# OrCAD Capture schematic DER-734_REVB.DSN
size B; title: DER-734 RevB; rev: RevB
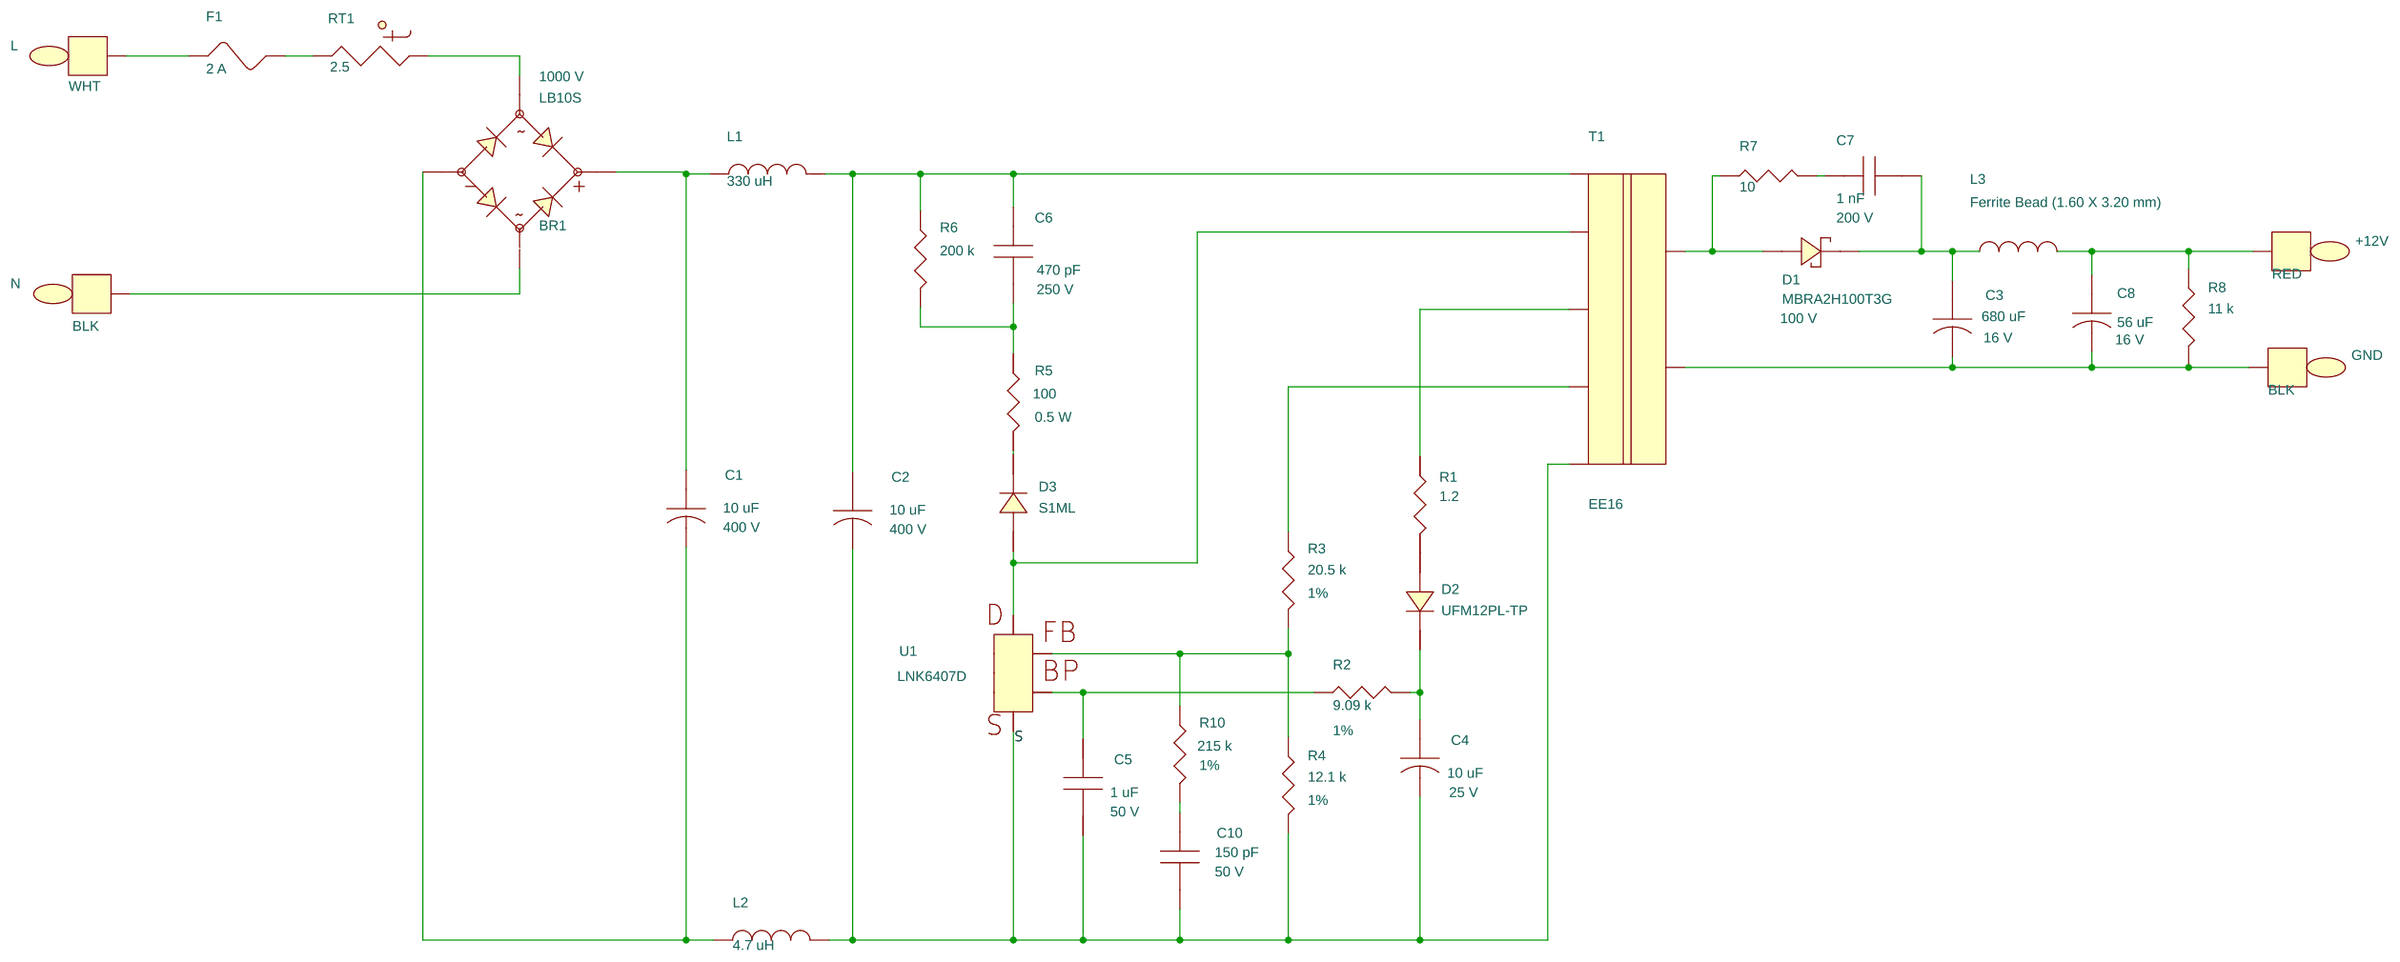
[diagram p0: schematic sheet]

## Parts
+12V  RED  [pitpkeystone100x100]
BR1  LB10S  [pismd_SOPA-4]
C1  10 uF  [pipolcapcyld400ls200040]
C2  10 uF  [pipolcapcyld400ls200040]
C3  680 uF  [pipolcapcyld400ls200040]
C4  10 uF  [pipolcapclyd5mmls2mm025]
C5  1 uF  [pismc0805]
C6  470 pF  [pismc0805]
C7  1 nF  [pismc0805]
C8  56 uF  [pipolcapclyd200ls80030]
C10  150 pF  [pismc0603]
D1  MBRA2H100T3G  [pismdo214ac12]
D2  UFM12PL-TP  [pi_sm_sod-123_12]
D3  S1ML  [pi_sm_sod-123_12]
F1  2 A  [pi_rst_microfuse]
GND  BLK  [pitpkeystone100x100]
L  WHT  [pitpkeystone100x100]
L1  330 uH  [pichoketokinvd276h413ls158d030]
L2  4.7 uH  [pismr0805]
L3  Ferrite Bead (1.60 X 3.20 mm)  [pismferritebead1206]
N  BLK  [pitpkeystone100x100]
R1  1.2  [pismr0805]
R2  9.09 k  [pismr0805]
R3  20.5 k  [pismr0603]
R4  12.1 k  [pismr0603]
R5  100  [pismr1210]
R6  200 k  [pismr1206]
R7  10  [pismr0805]
R8  11 k  [pismr1206]
R10  215 k  [pismr0603]
RT1  2.5  [pi_rad150x300ls200d030]
T1  EE16  [pi_bobbin_ee16_7p]
U1  LNK6407D  [pismso8dnshort5678]

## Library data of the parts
+12V = TESTPOINT: Part Number: 35-00080-00
BR1 = DIODE_BRIDGE_+~~-: ALT_SYMBOLS: pi_sm_soic4_slot; Disp_Voltage: 1000 V; FPLIST: pismd_SOPA-4,pi_sm_soic4_slot; Part Number: 15-01178-00
C1 C2 = CAP_POL: Disp_Voltage: 400 V; Part Number: 20-09049-00; Voltage: 400 V
C3 = CAP_POL: ALT_SYMBOLS: pipolcapclyd395x630ls200030h; Disp_Voltage: 16 V; FPLIST: pipolcapcyld400ls200040,pipolcapclyd395x630ls200030h; Part Number: 20-00018-00; Voltage: 16 V
C4 = CAP_POL: Disp_Voltage: 25 V; Part Number: 20-09124-00; Voltage: 25 V
C5 = CAP_NP: Disp_Voltage: 50 V; Part Number: 20-09146-00; Voltage: 50 V
C6 = CAP_NP: Disp_Voltage: 250 V; Part Number: 20-01001-00; Voltage: 250 V
C7 = CAP_NP: ALT_SYMBOLS: pismc0805_1; Disp_Voltage: 200 V; FPLIST: pismc0805,pismc0805_1; Part Number: 20-00737-00; Voltage: 200 V
C8 = CAP_POL: Disp_Voltage: 16 V; Part Number: 20-00877-00; Voltage: 16 V
C10 = CAP_NP: Disp_Voltage: 50 V; Part Number: 20-09123-00; Voltage: 50 V
D1 = DIODE_SCHOTTKY: Disp_Voltage: 100 V; Part Number: 15-01286-00
D2 = DIODE: Part Number: 16-00008-00
D3 = DIODE: Part Number: 15-01027-00
F1 = FUSE: ALT_SYMBOLS: pirstmicrofusehoz; FPLIST: pi_rst_microfuse,pirstmicrofusehoz; Part Number: 40-00021-00
GND N = TESTPOINT: Part Number: 35-00079-00
L = TESTPOINT: Part Number: 35-00081-00
L1 = INDUCTOR: Part Number: 30-00075-00
L2 = INDUCTOR: Part Number: 30-00372-00
L3 = INDUCTOR_BEAD: Part Number: 30-00489-00
R1 = R: Part Number: 05-01449-00
R2 = R: Disp_Tol: 1%; Part Number: 05-03397-00
R3 = R: Disp_Tol: 1%; Part Number: 05-03214-00
R4 = R: Disp_Tol: 1%; Part Number: 05-03190-00
R5 = R: Disp_Power: 0.5 W; Part Number: 05-05428-00
R6 = R: Part Number: 05-01407-00
R7 = R: Part Number: 05-01471-00
R8 = R: Part Number: 05-01377-00
R10 = R: Disp_Tol: 1%; Part Number: 05-01206-00
RT1 = THERMISTOR: ALT_SYMBOLS: pirad400x300ls200040_h; FPLIST: pi_rad150x300ls200d030,pirad400x300ls200040_h; Part Number: 90-00040-00
T1 = BEE16_7P_2: Part Number: 25-01015-00
U1 = LNK6407: Part Number: 10-00659-00

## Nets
S: C2.2 C4.2 C5.2 C10.2 L2.2 R4.2 T1.3 U1.5(S)
SOURCE: U1.6(SOURCE) U1.7(SOURCE) U1.8(SOURCE)
N00231: BR1.3 RT1.2
N00241: BR1.2 N.1
N00354: BR1.1 C1.1 L1.1
N00466: C2.1 C6.1 L1.2 R6.1 T1.7
N00504: BR1.4 C1.2 L2.1
N01033: C5.1 R2.1 U1.2(BP)
N01924: C3.1 C7.2 D1.1 L3.1
N01931: C3.2 C8.2 GND.1 R8.2 T1.1
N02333: C4.1 D2.1 R2.2
N03183: R3.2 R4.1 R10.1 U1.1(FB)
N03289: R3.1 T1.4
N03434: D3.1 R5.2
N04514: D3.2 T1.6 U1.4(D)
N04626: C6.2 R5.1 R6.2
N06055: C7.1 R7.2
N06246: D1.2 R7.1 T1.2
N06290: +12V.1 C8.1 L3.2 R8.1
N12001: F1.2 RT1.1
N12005: F1.1 L.1
N16793: R1.1 T1.5
N21336: C10.1 R10.2
N33317: D2.2 R1.2
